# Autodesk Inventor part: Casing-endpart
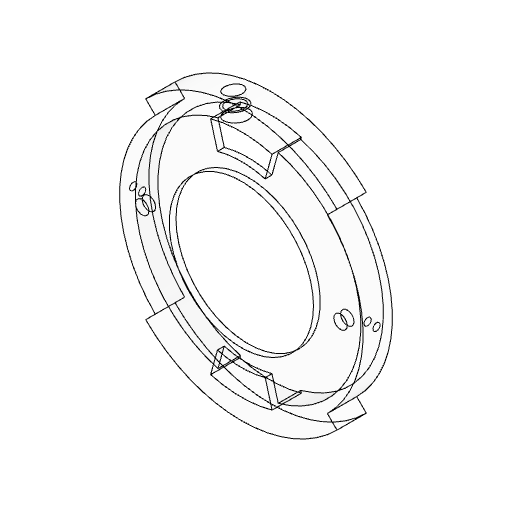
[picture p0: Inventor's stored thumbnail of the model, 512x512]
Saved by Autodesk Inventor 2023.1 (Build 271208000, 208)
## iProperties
Created: 2020-01
Part Number: Casing-endpart
Material: Polycarbonate, Clear
Document SubType Name: Modeling
Designer: ftrauzettel
Density: 1.2 g/cm^3
Appearance: Polycarbonate - Clear
Sending System: SolidWorks 2016
Last Author: Pam
Last Saved: 2020-10-15
Author: ftrauzettel
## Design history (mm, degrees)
feature "Cut-Extrude9"
body "Solid1"
